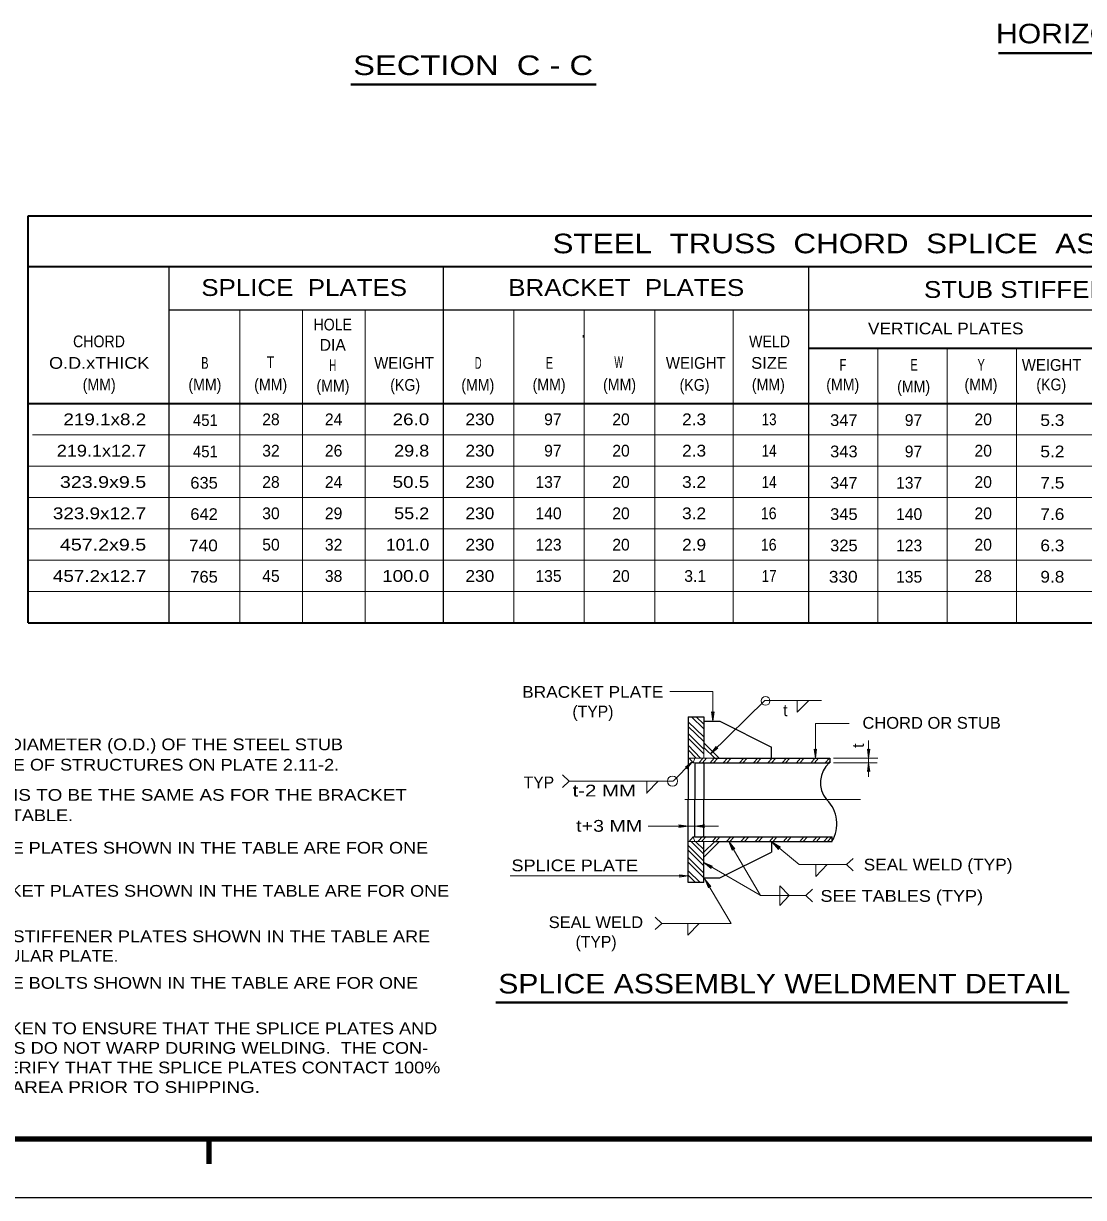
# Model space of a CAD drawing. Extents: x 312601.858 to 312602.699, y 144420.109 to 144420.704.
# Drawn here: x 312602.2309 to 312602.5016, y 144420.1095 to 144420.4093 of the extents above; entities that cross this region are included whole.
import ezdxf
from ezdxf.enums import TextEntityAlignment as Align

# ---------------------------------------------------------------- set-up
doc = ezdxf.new("R2010")
doc.units = 0
doc.header["$LTSCALE"] = 0.0012
doc.linetypes.add('DOT_DASHED', pattern=[7.7, 5, -1.2, 0.3, -1.2])
doc.linetypes.add('LONG_DASHED', pattern=[7.5, 6, -1.5])
for name, color, linetype, lineweight in [('1', 7, 'Continuous', 13), ('2', 7, 'Continuous', 25), ('39', 7, 'Continuous', 13)]:
    doc.layers.add(name, color=color, linetype=linetype, lineweight=lineweight)

msp = doc.modelspace()

# ---------------------------------------------------------------- hatches: boundary and pattern name
at = {"layer": '39'}
for points in [[(312602.4069, 144420.2333), (312602.4073, 144420.2335), (312602.4069, 144420.2311), (312602.4066, 144420.2335)], [(312602.4078, 144420.2243), (312602.4082, 144420.2242), (312602.4063, 144420.2228), (312602.4078, 144420.2247)], [(312602.3984, 144420.2043), (312602.3982, 144420.2047), (312602.4006, 144420.2043), (312602.3982, 144420.204)], [(312602.4046, 144420.2043), (312602.4048, 144420.204), (312602.4024, 144420.2043), (312602.4048, 144420.2047)], [(312602.4121, 144420.1985), (312602.4119, 144420.1982), (312602.411, 144420.2004), (312602.4125, 144420.1985)], [(312602.4238, 144420.1988), (312602.4237, 144420.1984), (312602.4221, 144420.2002), (312602.4242, 144420.199)], [(312602.4065, 144420.1939), (312602.4065, 144420.1935), (312602.4046, 144420.195), (312602.4068, 144420.1941)], [(312602.406, 144420.1889), (312602.4058, 144420.1886), (312602.4049, 144420.1908), (312602.4064, 144420.1889)]]:
    msp.add_hatch(color=256, dxfattribs=at).paths.add_polyline_path(points)

# ---------------------------------------------------------------- linework, layer by layer
at = {"layer": '1', "lineweight": 40}
for p, q in [((312602.4799, 144420.4017), (312602.6249, 144420.4017)), ((312602.3145, 144420.3937), (312602.3771, 144420.3937)), ((312602.3515, 144420.1593), (312602.4975, 144420.1593))]:
    msp.add_line(p, q, dxfattribs=at)
at = {"layer": '1', "lineweight": 35}
for p, q in [((312602.2321, 144420.3602), (312602.6749, 144420.3602)), ((312602.2321, 144420.2562), (312602.2321, 144420.3602)), ((312602.2321, 144420.3472), (312602.6749, 144420.3472)), ((312602.4314, 144420.3264), (312602.5729, 144420.3264)), ((312602.2321, 144420.3122), (312602.6746, 144420.3122)), ((312602.2321, 144420.2562), (312602.6749, 144420.2562))]:
    msp.add_line(p, q, dxfattribs=at)
at = {"layer": '1', "lineweight": 25}
for p, q in [((312602.2681, 144420.2562), (312602.2681, 144420.3472)), ((312602.3381, 144420.2562), (312602.3381, 144420.3472)), ((312602.4314, 144420.2562), (312602.4314, 144420.3472)), ((312602.2681, 144420.3362), (312602.6749, 144420.3362)), ((312602.4006, 144420.2322), (312602.4006, 144420.2111)), ((312602.4006, 144420.2322), (312602.4046, 144420.2322)), ((312602.4046, 144420.2322), (312602.4046, 144420.2244)), ((312602.4046, 144420.2311), (312602.4087, 144420.2311)), ((312602.4087, 144420.2311), (312602.4219, 144420.2245)), ((312602.4074, 144420.2217), (312602.4368, 144420.2217)), ((312602.4219, 144420.2217), (312602.4219, 144420.2245)), ((312602.4368, 144420.2217), (312602.4368, 144420.2205)), ((312602.4023, 144420.2205), (312602.4368, 144420.2205)), ((312602.4023, 144420.2202), (312602.4023, 144420.2111)), ((312602.4365, 144420.2205), (312602.4368, 144420.2208)), ((312602.4023, 144420.2016), (312602.4023, 144420.2111)), ((312602.4023, 144420.2016), (312602.4374, 144420.2016)), ((312602.4374, 144420.2004), (312602.4374, 144420.2016)), ((312602.4046, 144420.1899), (312602.4046, 144420.2004)), ((312602.4219, 144420.2004), (312602.4374, 144420.2004))]:
    msp.add_line(p, q, dxfattribs=at)
at = {"layer": '1'}
for p, q in [((312602.2861, 144420.2562), (312602.2861, 144420.3362)), ((312602.3021, 144420.2562), (312602.3021, 144420.3362)), ((312602.3181, 144420.2562), (312602.3181, 144420.3362)), ((312602.3561, 144420.2562), (312602.3561, 144420.3362)), ((312602.3741, 144420.2562), (312602.3741, 144420.3362)), ((312602.3921, 144420.2562), (312602.3921, 144420.3362)), ((312602.4121, 144420.2562), (312602.4121, 144420.3362)), ((312602.3738, 144420.3291), (312602.3738, 144420.3297)), ((312602.4491, 144420.2562), (312602.4491, 144420.3264)), ((312602.4668, 144420.2562), (312602.4668, 144420.3264)), ((312602.4845, 144420.2562), (312602.4845, 144420.3264)), ((312602.2332, 144420.3042), (312602.6746, 144420.3042)), ((312602.2321, 144420.2962), (312602.6746, 144420.2962)), ((312602.2321, 144420.2882), (312602.6746, 144420.2882)), ((312602.2321, 144420.2802), (312602.6746, 144420.2802)), ((312602.2321, 144420.2722), (312602.6746, 144420.2722)), ((312602.2321, 144420.2642), (312602.6746, 144420.2642)), ((312602.4063, 144420.2228), (312602.4202, 144420.2364)), ((312602.4347, 144420.2364), (312602.4202, 144420.2364)), ((312602.4006, 144420.231), (312602.4046, 144420.2271)), ((312602.4015, 144420.2322), (312602.4046, 144420.2292)), ((312602.4027, 144420.2322), (312602.4046, 144420.2304)), ((312602.4006, 144420.2298), (312602.4046, 144420.2259)), ((312602.4006, 144420.228), (312602.4046, 144420.224)), ((312602.4006, 144420.2268), (312602.4046, 144420.2228)), ((312602.4006, 144420.225), (312602.4038, 144420.2217)), ((312602.4006, 144420.2238), (312602.4027, 144420.2217)), ((312602.4006, 144420.2217), (312602.4008, 144420.2217)), ((312602.4007, 144420.2217), (312602.4046, 144420.2217)), ((312602.4034, 144420.2205), (312602.4044, 144420.2217)), ((312602.4043, 144420.2205), (312602.4053, 144420.2217)), ((312602.4062, 144420.2205), (312602.4073, 144420.2217)), ((312602.4071, 144420.2205), (312602.4082, 144420.2217)), ((312602.4096, 144420.2205), (312602.4107, 144420.2217)), ((312602.4105, 144420.2205), (312602.4116, 144420.2217)), ((312602.4137, 144420.2205), (312602.4148, 144420.2217)), ((312602.4146, 144420.2205), (312602.4157, 144420.2217)), ((312602.4173, 144420.2205), (312602.4184, 144420.2217)), ((312602.4182, 144420.2205), (312602.4193, 144420.2217)), ((312602.421, 144420.2205), (312602.4221, 144420.2217)), ((312602.4219, 144420.2205), (312602.423, 144420.2217)), ((312602.4246, 144420.2205), (312602.4257, 144420.2217)), ((312602.4255, 144420.2205), (312602.4266, 144420.2217)), ((312602.4283, 144420.2205), (312602.4293, 144420.2217)), ((312602.4292, 144420.2205), (312602.4302, 144420.2217)), ((312602.432, 144420.2205), (312602.433, 144420.2217)), ((312602.4329, 144420.2205), (312602.4339, 144420.2217)), ((312602.4356, 144420.2205), (312602.4367, 144420.2217)), ((312602.4377, 144420.2217), (312602.4491, 144420.2217)), ((312602.3968, 144420.2158), (312602.4017, 144420.2208)), ((312602.4019, 144420.2205), (312602.4023, 144420.2205)), ((312602.4377, 144420.2205), (312602.4489, 144420.2205)), ((312602.3685, 144420.2174), (312602.3702, 144420.2158)), ((312602.3685, 144420.2142), (312602.3702, 144420.2158)), ((312602.3702, 144420.2158), (312602.3967, 144420.2158)), ((312602.393, 144420.2158), (312602.3901, 144420.2128)), ((312602.3901, 144420.2157), (312602.3901, 144420.2127)), ((312602.4019, 144420.2016), (312602.4023, 144420.2016)), ((312602.4043, 144420.2017), (312602.4032, 144420.2005)), ((312602.4052, 144420.2017), (312602.4041, 144420.2005)), ((312602.4078, 144420.2016), (312602.4068, 144420.2004)), ((312602.4087, 144420.2016), (312602.4077, 144420.2004)), ((312602.4115, 144420.2016), (312602.4104, 144420.2004)), ((312602.4124, 144420.2016), (312602.4113, 144420.2004)), ((312602.4152, 144420.2016), (312602.4141, 144420.2004)), ((312602.4161, 144420.2016), (312602.415, 144420.2004)), ((312602.4188, 144420.2016), (312602.4177, 144420.2004)), ((312602.4197, 144420.2016), (312602.4186, 144420.2004)), ((312602.4224, 144420.2016), (312602.4214, 144420.2004)), ((312602.426, 144420.2016), (312602.425, 144420.2004)), ((312602.4269, 144420.2016), (312602.4259, 144420.2004)), ((312602.4302, 144420.2016), (312602.4291, 144420.2004)), ((312602.4311, 144420.2016), (312602.43, 144420.2004)), ((312602.4335, 144420.2016), (312602.4325, 144420.2004)), ((312602.4344, 144420.2016), (312602.4334, 144420.2004)), ((312602.4364, 144420.2016), (312602.4353, 144420.2004)), ((312602.4373, 144420.2016), (312602.4362, 144420.2004)), ((312602.4045, 144420.2004), (312602.4006, 144420.2004)), ((312602.4046, 144420.1954), (312602.4006, 144420.1994)), ((312602.4046, 144420.1942), (312602.4006, 144420.1982)), ((312602.4046, 144420.1972), (312602.4014, 144420.2004)), ((312602.4046, 144420.1984), (312602.4025, 144420.2004)), ((312602.411, 144420.2004), (312602.4191, 144420.1866)), ((312602.429, 144420.1945), (312602.4221, 144420.2002)), ((312602.4361, 144420.2004), (312602.4362, 144420.2004)), ((312602.4046, 144420.1923), (312602.4006, 144420.1963)), ((312602.4046, 144420.1911), (312602.4006, 144420.1951)), ((312602.3552, 144420.1916), (312602.4006, 144420.1916)), ((312602.4037, 144420.1899), (312602.4006, 144420.1929)), ((312602.4025, 144420.1899), (312602.4006, 144420.1918)), ((312602.4413, 144420.1945), (312602.429, 144420.1945)), ((312602.4049, 144420.1908), (312602.4116, 144420.1795)), ((312602.4191, 144420.1866), (312602.4306, 144420.1866)), ((312602.3922, 144420.1811), (312602.3939, 144420.1795)), ((312602.3922, 144420.1779), (312602.3939, 144420.1795)), ((312602.3939, 144420.1795), (312602.4116, 144420.1795)), ((312602.4005, 144420.1795), (312602.4005, 144420.1765)), ((312602.4034, 144420.1795), (312602.4005, 144420.1765))]:
    msp.add_line(p, q, dxfattribs=at)
at = {"layer": '1', "linetype": 'LONG_DASHED', "lineweight": 25}
for p in [(312602.4046, 144420.2205), (312602.4046, 144420.2016)]:
    msp.add_line(p, (312602.4046, 144420.2111), dxfattribs=at)
at = {"layer": '1', "linetype": 'DOT_DASHED'}
msp.add_line((312602.3998, 144420.2111), (312602.4446, 144420.2111), dxfattribs=at)
at = {"layer": '1', "lineweight": 158}
msp.add_line((312602.2783, 144420.1181), (312602.2783, 144420.1245), dxfattribs=at)
at = {"layer": '1'}
for points in [[(312602.3959, 144420.2387), (312602.4069, 144420.2387), (312602.4069, 144420.2311)], [(312602.4417, 144420.2305), (312602.4331, 144420.2305), (312602.4331, 144420.2217)], [(312602.4467, 144420.2262), (312602.4467, 144420.2217), (312602.4467, 144420.2205), (312602.4467, 144420.2169)], [(312602.3904, 144420.2043), (312602.4006, 144420.2043), (312602.4023, 144420.2043), (312602.4084, 144420.2043)], [(312602.4233, 144420.2016), (312602.4223, 144420.2004), (312602.4223, 144420.2004), (312602.4219, 144420.2001), (312602.4219, 144420.2004)]]:
    msp.add_lwpolyline(points, dxfattribs=at)
for points in [[(312602.4009, 144420.2217), (312602.4019, 144420.2205), (312602.4023, 144420.2217)], [(312602.4046, 144420.2244), (312602.4046, 144420.2217), (312602.4074, 144420.2217)], [(312602.4334, 144420.224), (312602.4331, 144420.2217), (312602.4328, 144420.224), (312602.4331, 144420.2237)], [(312602.447, 144420.224), (312602.4467, 144420.2217), (312602.4464, 144420.224), (312602.4467, 144420.2237)], [(312602.3999, 144420.2194), (312602.4017, 144420.2208), (312602.4003, 144420.219), (312602.4003, 144420.2194)], [(312602.4464, 144420.2183), (312602.4467, 144420.2205), (312602.447, 144420.2183), (312602.4467, 144420.2185)], [(312602.4009, 144420.2004), (312602.4019, 144420.2016), (312602.4023, 144420.2004)], [(312602.4046, 144420.1977), (312602.4046, 144420.2004), (312602.4074, 144420.2004)], [(312602.3984, 144420.1919), (312602.4006, 144420.1916), (312602.3984, 144420.1913), (312602.3986, 144420.1916)], [(312602.4046, 144420.1911), (312602.405, 144420.1911), (312602.4046, 144420.1907)]]:
    msp.add_lwpolyline(points, close=True, dxfattribs=at)
at = {"layer": '1', "lineweight": 25}
for points in [[(312602.4046, 144420.1899), (312602.4006, 144420.1899), (312602.4006, 144420.2111)], [(312602.4046, 144420.1911), (312602.4087, 144420.1911), (312602.4219, 144420.1977)], [(312602.4074, 144420.2004), (312602.4219, 144420.2004), (312602.4219, 144420.1977)]]:
    msp.add_lwpolyline(points, dxfattribs=at)
at = {"layer": '1'}
msp.add_circle((312602.3966, 144420.2158), 0.0013, dxfattribs=at)
at = {"layer": '1', "lineweight": 25}
for centre, radius, start, end in [((312602.4411, 144420.21543), 0.00671, 130.4637, 219.6833), ((312602.4299, 144420.20489), 0.00869, 329.062, 45.3866)]:
    msp.add_arc(centre, radius, start, end, dxfattribs=at)
at = {"layer": '2'}
for p, q in [((312602.4085, 144420.2217), (312602.4046, 144420.2256)), ((312602.4046, 144420.1964), (312602.4086, 144420.2004))]:
    msp.add_line(p, q, dxfattribs=at)
at = {"layer": '2', "lineweight": 13}
msp.add_line((312602.4046, 144420.195), (312602.419, 144420.1867), dxfattribs=at)
for points in [[(312602.4285, 144420.2364), (312602.4285, 144420.2334), (312602.4314, 144420.2364)], [(312602.4332, 144420.1945), (312602.4332, 144420.1915), (312602.4361, 144420.1945)], [(312602.4324, 144420.1882), (312602.4307, 144420.1866), (312602.4324, 144420.185)]]:
    msp.add_lwpolyline(points, dxfattribs=at)
at = {"layer": '2'}
msp.add_lwpolyline([(312602.4428, 144420.1961), (312602.4411, 144420.1945), (312602.4428, 144420.1929)], dxfattribs=at)
at = {"layer": '2', "lineweight": 13}
msp.add_lwpolyline([(312602.424, 144420.1841), (312602.424, 144420.1866), (312602.424, 144420.1891), (312602.4264, 144420.1866)], close=True, dxfattribs=at)
msp.add_circle((312602.4204, 144420.2363), 0.00112, dxfattribs=at)
at = {"layer": '39', "lineweight": 158}
for p, q in [((312601.9088, 144420.1245), (312602.6838, 144420.1245)), ((312602.2783, 144420.1181), (312602.2783, 144420.1245))]:
    msp.add_line(p, q, dxfattribs=at)
at = {"layer": '39', "lineweight": 25}
for p, q in [((312602.452, 144420.1245), (312602.6838, 144420.1245)), ((312601.8578, 144420.1095), (312602.6988, 144420.1095))]:
    msp.add_line(p, q, dxfattribs=at)
at = {"layer": '39'}
for points in [[(312602.4069, 144420.2333), (312602.4073, 144420.2335), (312602.4069, 144420.2311), (312602.4066, 144420.2335)], [(312602.4078, 144420.2243), (312602.4082, 144420.2242), (312602.4063, 144420.2228), (312602.4078, 144420.2247)], [(312602.3984, 144420.2043), (312602.3982, 144420.2047), (312602.4006, 144420.2043), (312602.3982, 144420.204)], [(312602.4046, 144420.2043), (312602.4048, 144420.204), (312602.4024, 144420.2043), (312602.4048, 144420.2047)], [(312602.4121, 144420.1985), (312602.4119, 144420.1982), (312602.411, 144420.2004), (312602.4125, 144420.1985)], [(312602.4238, 144420.1988), (312602.4237, 144420.1984), (312602.4221, 144420.2002), (312602.4242, 144420.199)], [(312602.4065, 144420.1939), (312602.4065, 144420.1935), (312602.4046, 144420.195), (312602.4068, 144420.1941)], [(312602.406, 144420.1889), (312602.4058, 144420.1886), (312602.4049, 144420.1908), (312602.4064, 144420.1889)]]:
    msp.add_lwpolyline(points, close=True, dxfattribs=at)

# ---------------------------------------------------------------- texts
at = {"layer": '2'}
for s, height, width, p in [('HORIZONTAL STUB STIFFENER DETAIL', 0.005, 1.15, (312602.5523, 144420.4042)), ('SECTION  C - C', 0.005, 1.25, (312602.3457, 144420.3961)), ('STEEL  TRUSS  CHORD  SPLICE  ASSEMBLY', 0.005, 1.2, (312602.4518, 144420.3506)), ('SPLICE  PLATES', 0.0043, 1.15, (312602.30255, 144420.3397)), ('BRACKET  PLATES', 0.0043, 1.15, (312602.3848, 144420.3397)), ('STUB STIFFENER PLATES', 0.0043, 1.15, (312602.50255, 144420.3392)), ('HOLE', 0.003, 0.9, (312602.30985, 144420.3309)), ('VERTICAL PLATES', 0.003, 1.1, (312602.4664, 144420.3299)), ('CHORD', 0.003, 0.9, (312602.25015, 144420.3266)), ('WELD', 0.003, 0.9, (312602.4214, 144420.3266)), ('O.D.xTHICK', 0.003, 1.15, (312602.2502, 144420.3211)), ('B', 0.003, 0.7, (312602.2772, 144420.3211)), ('T', 0.003, 0.8, (312602.29395, 144420.3213)), ('H', 0.003, 0.6, (312602.30985, 144420.3205)), ('WEIGHT', 0.003, 0.95, (312602.32805, 144420.3211)), ('D', 0.003, 0.6, (312602.347, 144420.3211)), ('E', 0.003, 0.7, (312602.3652, 144420.3211)), ('W', 0.003, 0.6, (312602.3829, 144420.3213)), ('WEIGHT', 0.003, 0.95, (312602.40255, 144420.3211)), ('SIZE', 0.003, 1.05, (312602.4214, 144420.3211)), ('F', 0.003, 0.7, (312602.44015, 144420.3206)), ('E', 0.003, 0.7, (312602.4583, 144420.3206)), ('Y', 0.003, 0.7, (312602.47545, 144420.3206)), ('WEIGHT', 0.003, 0.95, (312602.49345, 144420.3206)), ('(MM)', 0.003, 0.9, (312602.2502, 144420.3156)), ('(MM)', 0.003, 0.9, (312602.2772, 144420.3156)), ('(MM)', 0.003, 0.9, (312602.294, 144420.3156)), ('(MM)', 0.003, 0.9, (312602.3099, 144420.3153)), ('(KG)', 0.003, 0.9, (312602.32835, 144420.3155)), ('(MM)', 0.003, 0.9, (312602.3469, 144420.3155)), ('(MM)', 0.003, 0.9, (312602.3651, 144420.3156)), ('(MM)', 0.003, 0.9, (312602.3831, 144420.3156)), ('(KG)', 0.003, 0.9, (312602.40225, 144420.3155)), ('(MM)', 0.003, 0.9, (312602.4211, 144420.3156)), ('(MM)', 0.003, 0.9, (312602.4401, 144420.3156)), ('(MM)', 0.003, 0.9, (312602.4582, 144420.3151)), ('(MM)', 0.003, 0.9, (312602.4754, 144420.3156)), ('(KG)', 0.003, 0.9, (312602.49335, 144420.3156)), ('BRACKET PLATE', 0.003, 1.1, (312602.37625, 144420.2371)), ('CHORD OR STUB', 0.003, 1.05, (312602.4628, 144420.2292)), ('t-2 MM', 0.003, 1.3, (312602.3792, 144420.2119)), ('t+3 MM', 0.003, 1.25, (312602.38045, 144420.2029)), ('SPLICE PLATE', 0.003, 1.15, (312602.37165, 144420.1928)), ('SEAL WELD (TYP)', 0.003, 1.1, (312602.46445, 144420.193)), ('SEAL WELD', 0.003, 1.05, (312602.37705, 144420.1783)), ('SPLICE ASSEMBLY WELDMENT DETAIL ', 0.005, 1.15, (312602.42625, 144420.1616))]:
    msp.add_text(s, height=height, dxfattribs=dict(at, width=width)).set_placement(p, align=Align.CENTER)
for s, p in [('DIA', (312602.30985, 144420.3257)), ('(TYP)', (312602.3763, 144420.2321)), ('t', (312602.42545, 144420.2324)), ('TYP', (312602.3625, 144420.214)), ('(TYP)', (312602.3771, 144420.1733))]:
    msp.add_text(s, height=0.003, dxfattribs=at).set_placement(p, align=Align.CENTER)
for s, width, p in [('219.1x8.2', 1.2, (312602.2622, 144420.3067)), ('451', 0.95, (312602.2805, 144420.3065)), ('26.0', 1.2, (312602.3345, 144420.3067)), ('230', 1.1, (312602.3511, 144420.3067)), ('2.3', 1.1, (312602.4052, 144420.3067)), ('13', 0.85, (312602.4232, 144420.3067)), ('347', 1.05, (312602.4439, 144420.3065)), ('5.3', 1.1, (312602.4967, 144420.3065)), ('219.1x12.7', 1.15, (312602.2622, 144420.2987)), ('451', 0.95, (312602.2805, 144420.2985)), ('29.8', 1.15, (312602.3345, 144420.2987)), ('230', 1.1, (312602.3511, 144420.2987)), ('2.3', 1.1, (312602.4052, 144420.2987)), ('14', 0.85, (312602.4232, 144420.2987)), ('343', 1.05, (312602.4439, 144420.2985)), ('5.2', 1.1, (312602.4967, 144420.2985)), ('323.9x9.5', 1.25, (312602.2622, 144420.2907)), ('635', 1.05, (312602.2805, 144420.2905)), ('50.5', 1.2, (312602.3345, 144420.2907)), ('230', 1.1, (312602.3511, 144420.2907)), ('3.2', 1.1, (312602.4052, 144420.2907)), ('14', 0.85, (312602.4232, 144420.2907)), ('347', 1.05, (312602.4439, 144420.2905)), ('7.5', 1.1, (312602.4967, 144420.2905)), ('323.9x12.7', 1.2, (312602.2622, 144420.2827)), ('642', 1.05, (312602.2805, 144420.2825)), ('55.2', 1.15, (312602.3345, 144420.2827)), ('230', 1.1, (312602.3511, 144420.2827)), ('3.2', 1.1, (312602.4052, 144420.2827)), ('16', 0.9, (312602.4232, 144420.2827)), ('345', 1.05, (312602.4439, 144420.2825)), ('7.6', 1.1, (312602.4967, 144420.2825)), ('457.2x9.5', 1.25, (312602.2622, 144420.2747)), ('740', 1.1, (312602.2805, 144420.2745)), ('101.0', 1.1, (312602.3345, 144420.2747)), ('230', 1.1, (312602.3511, 144420.2747)), ('2.9', 1.1, (312602.4052, 144420.2747)), ('16', 0.9, (312602.4232, 144420.2747)), ('325', 1.05, (312602.4439, 144420.2745)), ('6.3', 1.1, (312602.4967, 144420.2745)), ('457.2x12.7', 1.2, (312602.2622, 144420.2667)), ('765', 1.05, (312602.2805, 144420.2665)), ('100.0', 1.2, (312602.3345, 144420.2667)), ('230', 1.1, (312602.3511, 144420.2667)), ('17', 0.85, (312602.4232, 144420.2667)), ('330', 1.1, (312602.4439, 144420.2665)), ('9.8', 1.1, (312602.4967, 144420.2665))]:
    msp.add_text(s, height=0.003, dxfattribs=dict(at, width=width)).set_placement(p, align=Align.RIGHT)
for s, p in [('28', (312602.2963, 144420.3067)), ('24', (312602.3123, 144420.3067)), ('97', (312602.3683, 144420.3067)), ('20', (312602.3857, 144420.3067)), ('97', (312602.4604, 144420.3065)), ('20', (312602.4782, 144420.3067)), ('32', (312602.2963, 144420.2987)), ('26', (312602.3123, 144420.2987)), ('97', (312602.3683, 144420.2987)), ('20', (312602.3857, 144420.2987)), ('97', (312602.4604, 144420.2985)), ('20', (312602.4782, 144420.2987)), ('28', (312602.2963, 144420.2907)), ('24', (312602.3123, 144420.2907)), ('137', (312602.3683, 144420.2907)), ('20', (312602.3857, 144420.2907)), ('137', (312602.4604, 144420.2905)), ('20', (312602.4782, 144420.2907)), ('30', (312602.2963, 144420.2827)), ('29', (312602.3123, 144420.2827)), ('140', (312602.3683, 144420.2827)), ('20', (312602.3857, 144420.2827)), ('140', (312602.4604, 144420.2825)), ('20', (312602.4782, 144420.2827)), ('50', (312602.2963, 144420.2747)), ('32', (312602.3123, 144420.2747)), ('123', (312602.3683, 144420.2747)), ('20', (312602.3857, 144420.2747)), ('123', (312602.4604, 144420.2745)), ('20', (312602.4782, 144420.2747)), ('45', (312602.2963, 144420.2667)), ('38', (312602.3123, 144420.2667)), ('135', (312602.3683, 144420.2667)), ('20', (312602.3857, 144420.2667)), ('3.1', (312602.4052, 144420.2667)), ('135', (312602.4604, 144420.2665)), ('28', (312602.4782, 144420.2667))]:
    msp.add_text(s, height=0.003, dxfattribs=at).set_placement(p, align=Align.RIGHT)
for s, width, p in [('FOR THE OUTSIDE DIAMETER (O.D.) OF THE STEEL STUB', 1.15, (312602.1838, 144420.2237)), ('PIPE SEE SCHEDULE OF STRUCTURES ON PLATE 2.11-2.', 1.15, (312602.1838, 144420.2185)), ('FILLET WELD SIZE IS TO BE THE SAME AS FOR THE BRACKET', 1.2, (312602.1838, 144420.2108)), ('PLATES SHOWN IN TABLE.', 1.15, (312602.1838, 144420.2056)), ('WEIGHTS OF SPLICE PLATES SHOWN IN THE TABLE ARE FOR ONE', 1.15, (312602.184, 144420.1973)), ('WEIGHTS OF BRACKET PLATES SHOWN IN THE TABLE ARE FOR ONE', 1.15, (312602.184, 144420.1863)), ('SEE TABLES (TYP)', 1.15, (312602.4344, 144420.185)), ('WEIGHTS OF STUB STIFFENER PLATES SHOWN IN THE TABLE ARE', 1.15, (312602.184, 144420.1747)), ('FOR ONE RECTANGULAR PLATE.', 1.1, (312602.184, 144420.1697)), ('WEIGHTS OF SPLICE BOLTS SHOWN IN THE TABLE ARE FOR ONE ', 1.15, (312602.184, 144420.1628)), ('CARE SHALL BE TAKEN TO ENSURE THAT THE SPLICE PLATES AND', 1.15, (312602.184, 144420.1512)), ('THE TRUSS CHORDS DO NOT WARP DURING WELDING.  THE CON-', 1.15, (312602.184, 144420.1462)), ('TRACTOR SHALL VERIFY THAT THE SPLICE PLATES CONTACT 100%', 1.15, (312602.184, 144420.1412)), ('OF THEIR MATING AREA PRIOR TO SHIPPING.', 1.2, (312602.184, 144420.1362))]:
    msp.add_text(s, height=0.003, dxfattribs=dict(at, width=width)).set_placement(p)
msp.add_text('t', height=0.003, rotation=90, dxfattribs=at).set_placement((312602.4455, 144420.22485), align=Align.CENTER)

doc.saveas('drawing.dxf')
